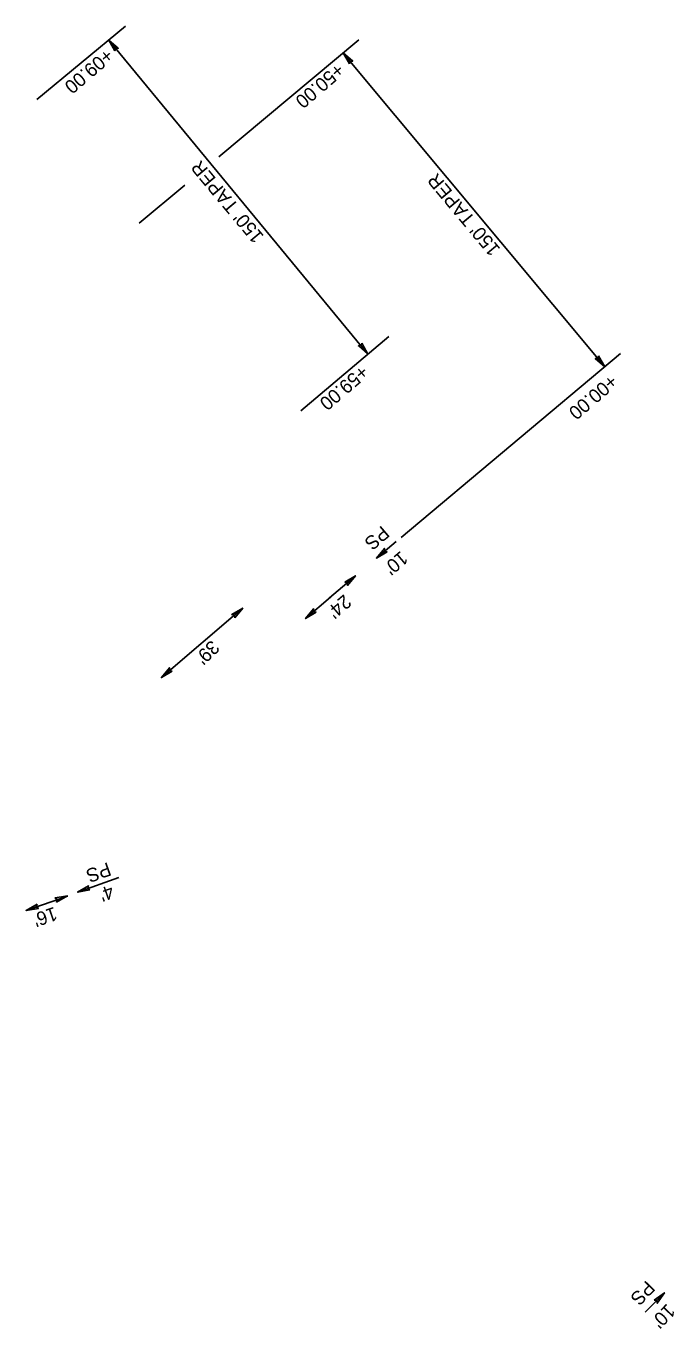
# Model space of a CAD drawing. Extents: x 1262642 to 1268358, y 767825 to 773481.
# Drawn here: x 1263238.7 to 1263475.3, y 769098.8 to 769574.6 of the extents above; entities that cross this region are included whole.
import ezdxf

# ---------------------------------------------------------------- set-up
doc = ezdxf.new("R2010")
doc.units = 0
for name, color, linetype in [('Prop Dimension', 7, 'Continuous'), ('Prop Dimension Text', 7, 'Continuous'), ('Prop Terminator CELL', 7, 'Continuous')]:
    doc.layers.add(name, color=color, linetype=linetype)

msp = doc.modelspace()

# ---------------------------------------------------------------- linework, layer by layer
at = {"layer": 'Prop Dimension'}
for p, q in [((1263242.59, 769547.82), (1263275.05, 769574.62)), ((1263363.54, 769454.81), (1263268.85, 769569.5)), ((1263371.16, 769461.27), (1263339.06, 769434.05))]:
    msp.add_line(p, q, dxfattribs=at)
for points in [[(1263271.14, 769565.55), (1263268.85, 769569.5), (1263272.36, 769566.54), (1263271.38, 769566.47)], [(1263356.77, 769560.83), (1263354.49, 769564.78), (1263358, 769561.82), (1263357.02, 769561.75)], [(1263361.26, 769458.76), (1263363.54, 769454.81), (1263360.03, 769457.77), (1263361.01, 769457.84)], [(1263447.78, 769454.17), (1263450.07, 769450.22), (1263446.56, 769453.18), (1263447.54, 769453.25)], [(1263370.56, 769382.61), (1263366.62, 769380.29), (1263369.56, 769383.83), (1263369.64, 769382.84)]]:
    msp.add_lwpolyline(points, close=True, dxfattribs=at)
at = {"layer": 'Prop Dimension Text'}
for p, q in [((1263309.03, 769526.85), (1263360.24, 769569.58)), ((1263450.07, 769450.22), (1263354.5, 769564.77)), ((1263279.94, 769502.58), (1263296.62, 769516.5)), ((1263375.65, 769387.86), (1263455.81, 769455.03)), ((1263366.62, 769380.29), (1263373.83, 769386.33)), ((1263358.96, 769373.87), (1263349.52, 769365.78)), ((1263349.85, 769366.06), (1263340.73, 769358.25)), ((1263288.11, 769336.69), (1263317.77, 769362.02)), ((1263257.54, 769258.33), (1263272.61, 769263.69)), ((1263253.8, 769256.9), (1263238.68, 769251.67)), ((1263464.76, 769104.86), (1263471.78, 769111.98))]:
    msp.add_line(p, q, dxfattribs=at)
for points in [[(1263355.04, 769371.53), (1263358.96, 769373.87), (1263356.04, 769370.32), (1263355.96, 769371.3)], [(1263314.86, 769358.49), (1263317.79, 769362), (1263313.82, 769359.68), (1263314.78, 769359.44)], [(1263344.66, 769360.59), (1263340.73, 769358.25), (1263343.65, 769361.81), (1263343.73, 769360.82)], [(1263292.04, 769339.03), (1263288.11, 769336.69), (1263291.03, 769340.24), (1263291.12, 769339.26)], [(1263468.08, 769109.3), (1263471.78, 769111.98), (1263469.19, 769108.18), (1263469.02, 769109.15)]]:
    msp.add_lwpolyline(points, close=True, dxfattribs=at)
at = {"layer": 'Prop Terminator CELL'}
for points in [[(1263262.02, 769259.1), (1263257.52, 769258.34), (1263261.52, 769260.6), (1263261.24, 769259.65)], [(1263249.82, 769254.7), (1263253.81, 769256.91), (1263249.28, 769256.18), (1263250.08, 769255.61)], [(1263242.68, 769253.87), (1263238.68, 769251.67), (1263243.22, 769252.39), (1263242.41, 769252.96)]]:
    msp.add_lwpolyline(points, close=True, dxfattribs=at)

# ---------------------------------------------------------------- texts
at = {"layer": 'Prop Dimension'}
for s, rotation, p in [('PS', 199.5593, (1263268.58, 769269.33)), ("4'", 199.5593, (1263269.66, 769261.1)), ("16'", 199.0766, (1263249.01, 769253.05))]:
    msp.add_text(s, height=5, rotation=rotation, dxfattribs=at).set_placement(p)
at = {"layer": 'Prop Dimension Text'}
for s, rotation, p in [('+09.00', 220.5946, (1263267.94, 769566.72)), ('+50.00', 220.5946, (1263352.26, 769561.39)), ("150' TAPER", 129.8409, (1263325.76, 769497.91)), ("150' TAPER", 129.8409, (1263412.12, 769493.22)), ('+59.00', 220.5946, (1263361.09, 769451.11)), ('+00.00', 220.5946, (1263452.06, 769447.69)), ('PS', 220.2339, (1263368.65, 769392.41)), ("10'", 220.2339, (1263375.51, 769383.18)), ("24'", 220.5946, (1263354.8, 769367.3)), ("39'", 223.989, (1263306.35, 769350.64)), ('PS', 225.6948, (1263465.23, 769116.78)), ("10'", 225.6948, (1263472.72, 769108.28))]:
    msp.add_text(s, height=5, rotation=rotation, dxfattribs=at).set_placement(p)

doc.saveas('drawing.dxf')
